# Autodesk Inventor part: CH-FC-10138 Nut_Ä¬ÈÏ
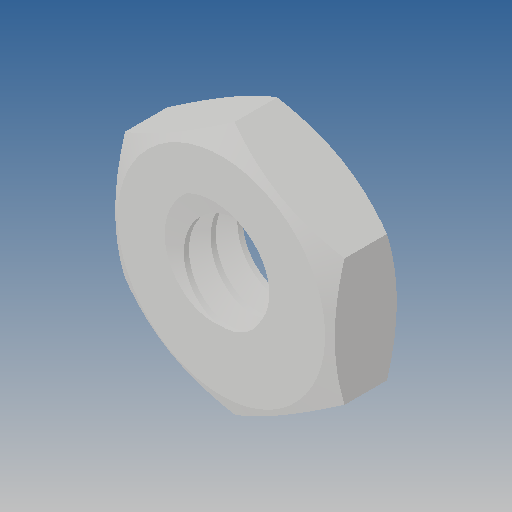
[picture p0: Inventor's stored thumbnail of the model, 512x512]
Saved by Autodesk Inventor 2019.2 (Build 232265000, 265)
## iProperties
Created: 2010-06
Part Number: CH-FC-10138 Nut_Ä¬ÈÏ
Material: Ogólny
Document SubType Name: Modeling
Designer: CADENGINEERING4
Density: 1 g/cm^3
Appearance: Domyślna
Author: CADENGINEERING4
Revision Number: ÈÎºÎ
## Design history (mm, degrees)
feature "NONE"
node "Bryła1"
